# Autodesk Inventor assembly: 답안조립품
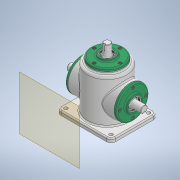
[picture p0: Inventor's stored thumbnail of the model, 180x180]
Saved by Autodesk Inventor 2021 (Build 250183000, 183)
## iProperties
Created: 2021-02
Part Number: 답안조립품
Document SubType Name: Assembly
Designer: 201-12
Author: 201-12
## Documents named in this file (16)
- C:\Users\201-12\Downloads\710214V1003\답안조립품.iam
- C:\Users\201-12\Downloads\710214V1003\본체.ipt
- C:\Users\201-12\Downloads\710214V1003\커버.ipt
- C:\Users\201-12\Downloads\710214V1003\베어링 6203.ipt
- C:\Users\201-12\Downloads\710214V1003\오일 실.ipt
- 오일 실.ipt
- C:\Users\201-12\Downloads\710214V1003\메인 축.ipt
- 메인 축.ipt
- C:\Users\201-12\Downloads\710214V1003\키 5x5.ipt
- C:\Users\201-12\Downloads\710214V1003\메인 베벨기어.ipt
- C:\Users\201-12\Downloads\710214V1003\서브 축.ipt
- 서브 축.ipt
- C:\Users\201-12\Downloads\710214V1003\키 4x4.ipt
- C:\Users\201-12\Downloads\710214V1003\서브 베벨기어.ipt
- C:\Users\201-12\Downloads\710214V1003\볼트 M4.ipt
- 볼트 M4.ipt
